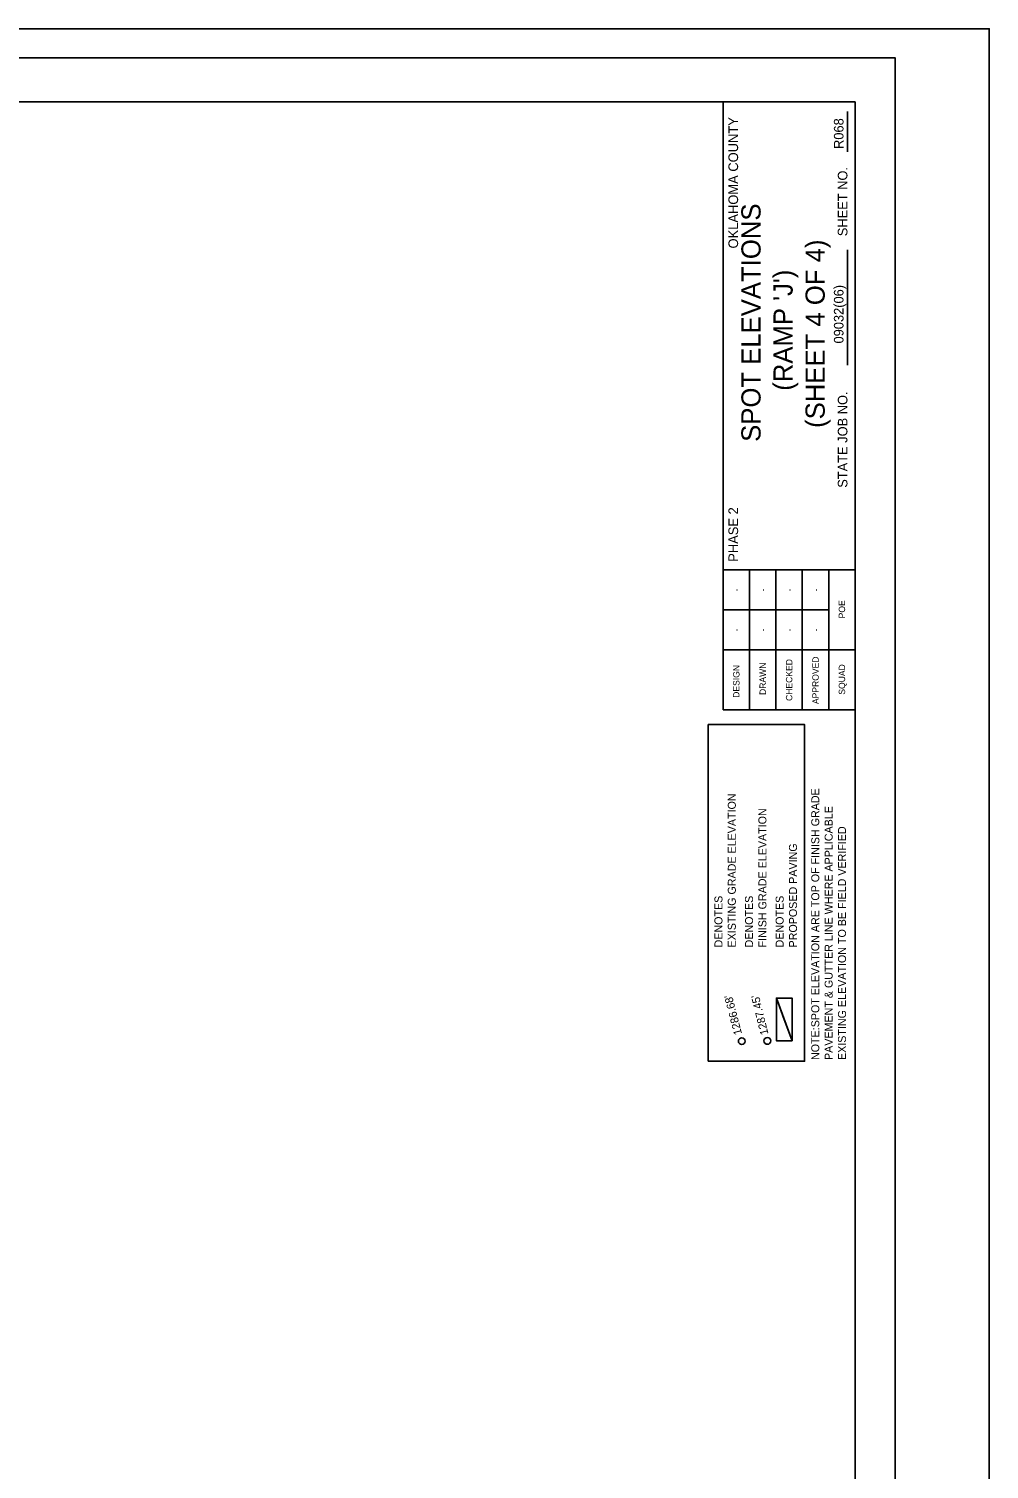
# Model space of a CAD drawing. Extents: x 2150652 to 2151372, y 143470 to 144550.
# Drawn here: x 2151012 to 2151372, y 144010 to 144550 of the extents above; entities that cross this region are included whole.
import ezdxf

# ---------------------------------------------------------------- set-up
doc = ezdxf.new("R2010")
doc.units = 0
for name, color, linetype in [('EX_Align_Text', 7, 'Continuous'), ('INR_Tracking', 7, 'Continuous'), ('PR_Improvements_Txt', 7, 'Continuous'), ('PR_Misc_Improvement', 7, 'Continuous'), ('PR_Pattern_Area_Pavement_Phase_3', 7, 'Continuous'), ('PR_Shading_1', 7, 'Continuous'), ('SHT_Plot_Shape_Half', 7, 'Continuous'), ('SHT_Sheet_Border', 7, 'Continuous'), ('SHT_Standard_Sheet_Txt', 7, 'Continuous'), ('TOPO_Curb Gut', 7, 'Continuous'), ('TOPO_Fence', 7, 'Continuous'), ('TOPO_RR Rail', 7, 'Continuous')]:
    doc.layers.add(name, color=color, linetype=linetype)

msp = doc.modelspace()

# ---------------------------------------------------------------- linework, layer by layer
at = {"layer": 'PR_Improvements_Txt'}
for points in [[(2151266.91, 144163.36), (2151266.91, 144289.57), (2151303.02, 144289.57), (2151303.02, 144163.36)], [(2151292.52, 144171.02), (2151292.52, 144187.04), (2151298.35, 144187.04), (2151298.35, 144171.02)]]:
    msp.add_lwpolyline(points, close=True, dxfattribs=at)
at = {"layer": 'PR_Misc_Improvement'}
for centre in [(2151279.49, 144170.86), (2151289.1, 144170.97)]:
    msp.add_circle(centre, 1.27, dxfattribs=at)
at = {"layer": 'PR_Pattern_Area_Pavement_Phase_3'}
msp.add_line((2151298.35, 144171.02), (2151292.52, 144187.04), dxfattribs=at)
at = {"layer": 'PR_Shading_1'}
msp.add_lwpolyline([(2151298.35, 144171.02), (2151295.43, 144179.03), (2151292.52, 144187.04), (2151292.52, 144171.02), (2151298.35, 144171.02)], dxfattribs=at)
at = {"layer": 'SHT_Plot_Shape_Half'}
msp.add_lwpolyline([(2150677, 143519.53), (2150677, 144539.53), (2151337, 144539.53), (2151337, 143519.53)], close=True, dxfattribs=at)
at = {"layer": 'SHT_Sheet_Border'}
for p, q in [((2151272.5, 144295.03), (2151272.5, 144523.03)), ((2151322, 144347.53), (2151272.48, 144347.53)), ((2151322, 144295.03), (2151272.5, 144295.03))]:
    msp.add_line(p, q, dxfattribs=at)
msp.add_lwpolyline([(2151322, 144523.03), (2151322, 143578.03), (2150692, 143578.03), (2150692, 144523.03)], close=True, dxfattribs=at)
at = {"layer": 'TOPO_Curb Gut'}
msp.add_lwpolyline([(2150652.25, 143470.4), (2150652.25, 144550.4), (2151372.25, 144550.4), (2151372.25, 143470.4)], close=True, dxfattribs=at)
at = {"layer": 'TOPO_Fence'}
for p, q in [((2151319.11, 144504.29), (2151319.11, 144519.37)), ((2151319.12, 144424.35), (2151319.11, 144467.56)), ((2151312.09, 144332.53), (2151272.48, 144332.53)), ((2151322, 144317.53), (2151272.48, 144317.53))]:
    msp.add_line(p, q, dxfattribs=at)
for points in [[(2151282.4, 144347.53), (2151282.4, 144295.03)], [(2151292.3, 144347.53), (2151292.3, 144295.03)], [(2151302.2, 144347.53), (2151302.2, 144295.03)], [(2151312.1, 144347.53), (2151312.1, 144295.03)]]:
    msp.add_lwpolyline(points, dxfattribs=at)
at = {"layer": 'TOPO_RR Rail'}
msp.add_lwpolyline([(2151292.52, 144187.04), (2151295.43, 144179.03), (2151298.35, 144171.02), (2151298.35, 144187.04), (2151292.52, 144187.04)], dxfattribs=at)

# ---------------------------------------------------------------- texts
at = {"layer": 'EX_Align_Text'}
msp.add_text("1286.68' ", height=3, rotation=104.6073, dxfattribs=at).set_placement((2151279.62, 144173.66))
at = {"layer": 'INR_Tracking'}
msp.add_text("1287.45' ", height=3, rotation=103.8066, dxfattribs=at).set_placement((2151289.53, 144173.61))
at = {"layer": 'PR_Improvements_Txt'}
for s, p in [('EXISTING GRADE ELEVATION', (2151277.27, 144206.01)), ('NOTE:SPOT ELEVATION ARE TOP OF FINISH GRADE', (2151308.56, 144163.81)), ('FINISH GRADE ELEVATION', (2151288.74, 144206.01)), ('PAVEMENT & GUTTER LINE WHERE APPLICABLE', (2151313.57, 144163.81)), ('EXISTING ELEVATION TO BE FIELD VERIFIED', (2151318.58, 144163.81)), ('PROPOSED PAVING', (2151300.21, 144206.01)), ('DENOTES', (2151272.26, 144206.01)), ('DENOTES', (2151283.73, 144206.01)), ('DENOTES', (2151295.2, 144206.01))]:
    msp.add_text(s, height=3, rotation=90, dxfattribs=at).set_placement(p)
at = {"layer": 'SHT_Standard_Sheet_Txt'}
for s, height, p in [('OKLAHOMA COUNTY', 3.6211, (2151278.13, 144468.05)), ('R068', 3.6, (2151317.64, 144505.36)), ('SHEET NO. ', 3.6, (2151319.11, 144472.65)), ('SPOT ELEVATIONS', 7.2, (2151286.56, 144395.56)), ('(SHEET 4 OF 4)', 7.2, (2151310.61, 144400.78)), ("(RAMP 'J')", 7.2, (2151298.58, 144414.71)), ('09032(06)', 3.6, (2151317.64, 144432.43)), ('STATE JOB NO.', 3.6, (2151319.11, 144378.34)), ('PHASE 2', 3.621, (2151278.13, 144350.59)), ('-', 2.4, (2151278.64, 144339.44)), ('-', 2.4, (2151288.56, 144339.44)), ('-', 2.4, (2151298.46, 144339.44)), ('-', 2.4, (2151308.36, 144339.44)), ('POE', 2.4, (2151318.25, 144329.38)), ('-', 2.4, (2151278.64, 144324.44)), ('-', 2.4, (2151288.56, 144324.44)), ('-', 2.4, (2151298.46, 144324.44)), ('-', 2.4, (2151308.36, 144324.44)), ('DESIGN', 2.4, (2151278.65, 144299.59)), ('DRAWN', 2.4, (2151288.55, 144300.67)), ('CHECKED', 2.4, (2151298.45, 144298.42)), ('APPROVED', 2.4, (2151308.35, 144297.24)), ('SQUAD', 2.4, (2151318.25, 144300.77))]:
    msp.add_text(s, height=height, rotation=90, dxfattribs=at).set_placement(p)

doc.saveas('drawing.dxf')
